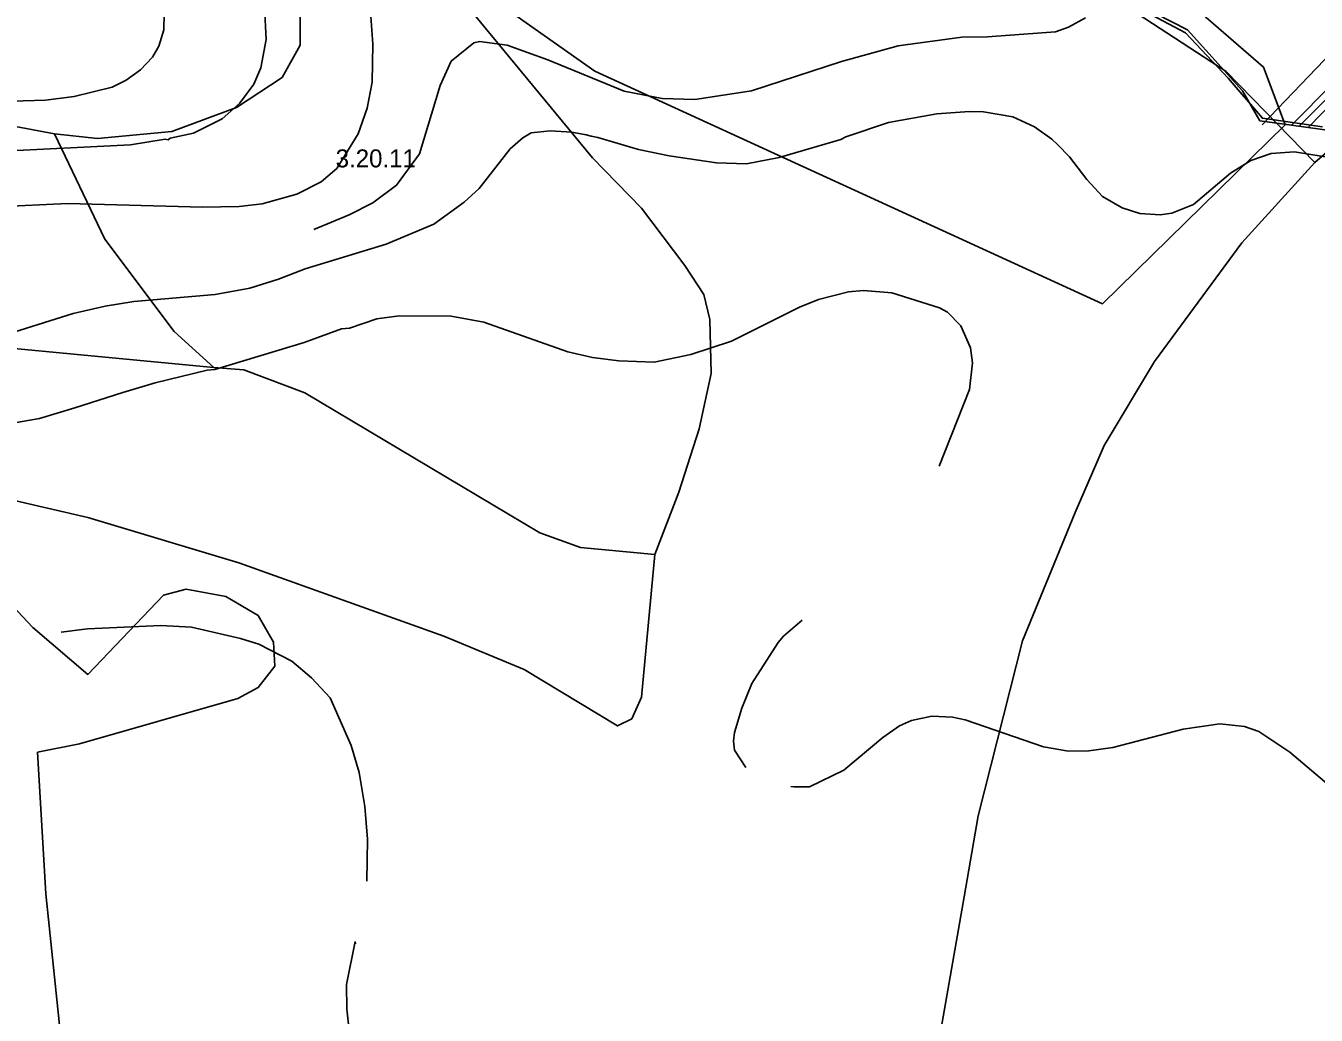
# Model space of a CAD drawing. Extents: x -662500 to -655523, y -1056000 to -1049993.
# Drawn here: x -661264 to -660726, y -1053965 to -1053552 of the extents above; entities that cross this region are included whole.
import ezdxf

# ---------------------------------------------------------------- set-up
doc = ezdxf.new("R2010")
doc.units = 0
for name, color, linetype in [('58', 7, 'Continuous'), ('Vrstva 1', 7, 'Continuous'), ('Vrstva 24', 7, 'Continuous'), ('Vrstva 32', 7, 'Continuous'), ('Vrstva 37', 7, 'Continuous'), ('Vrstva 5', 7, 'Continuous'), ('Vrstva 51', 7, 'Continuous'), ('Vrstva 7', 7, 'Continuous')]:
    doc.layers.add(name, color=color, linetype=linetype)

msp = doc.modelspace()

# ---------------------------------------------------------------- linework, layer by layer
at = {"layer": '58'}
msp.add_lwpolyline([(-660722.92, -1053594.62), (-660747.91, -1053591.01), (-660762.26, -1053574.33), (-660780.1, -1053555.32), (-660805.82, -1053541.62)], dxfattribs=at)
at = {"layer": 'Vrstva 1'}
for points in [[(-660749.01, -1053592.05), (-660756.28, -1053579.6), (-660779.23, -1053554.07), (-660805.9, -1053540.3)], [(-660438.94, -1053983.58), (-660410.34, -1053829.44), (-660408.79, -1053821.07), (-660408.56, -1053819.81), (-660407.77, -1053814.99), (-660398.86, -1053759.98), (-660378.28, -1053653.76), (-660412.36, -1053647.26), (-660481.41, -1053634.1), (-660522.43, -1053627.05), (-660591.82, -1053615.12), (-660653.75, -1053605.31), (-660728.84, -1053594.86), (-660735.74, -1053593.9), (-660749.01, -1053592.05)]]:
    msp.add_lwpolyline(points, dxfattribs=at)
at = {"layer": 'Vrstva 24'}
for points in [[(-661088, -1053355.5), (-661106, -1053352.5), (-661119, -1053355), (-661133.5, -1053361.5), (-661158.5, -1053380.5), (-661171.5, -1053398.5), (-661180, -1053425.5), (-661178.5, -1053461.5), (-661169.5, -1053488.5), (-661160, -1053506.5), (-661149.5, -1053542.5), (-661149.5, -1053560.5), (-661157, -1053574), (-661176, -1053586.5), (-661203, -1053596.5), (-661234, -1053599.5), (-661252, -1053597.5)], [(-661001.5, -1053773), (-660991.5, -1053747), (-660983, -1053720.5), (-660978, -1053697.5), (-660978.5, -1053675), (-660981, -1053664.5), (-660989, -1053652.5), (-661007, -1053628.5), (-661027.5, -1053607.5), (-661079.5, -1053544.5), (-661099.5, -1053509.5), (-661117, -1053463.5), (-661120.5, -1053436.5), (-661117, -1053400.5), (-661107.5, -1053378), (-661096, -1053362.5), (-661088, -1053355.5)], [(-660726, -1053609.5), (-660746.75, -1053588.19), (-660763, -1053571.5), (-660803, -1053545.5), (-660863.5, -1053530), (-660875.5, -1053525), (-660916, -1053497.5), (-660931, -1053485.5)], [(-660726, -1053609.5), (-660705.14, -1053591.51), (-660671.5, -1053562.5), (-660660, -1053547.5)], [(-661185.5, -1053695), (-661301, -1053684), (-661359, -1053670), (-661461.5, -1053632.5), (-661511.5, -1053619), (-661574.5, -1053608), (-661636, -1053600.5), (-661701, -1053596.5), (-661815.5, -1053587.5), (-661858, -1053587.5)], [(-661252, -1053597.5), (-661270.5, -1053594)], [(-661252, -1053597.5), (-661231, -1053641.5), (-661202, -1053680), (-661185.5, -1053695)], [(-660911, -1054178.5), (-660888, -1054130), (-660876.5, -1054089.5), (-660875.5, -1054053.5), (-660883, -1054011.5), (-660884.37, -1054000), (-660885.5, -1053990.5), (-660872.42, -1053915.83), (-660866.5, -1053882), (-660848, -1053809), (-660826, -1053755.5), (-660816.62, -1053733.62), (-660814, -1053727.5), (-660793, -1053692.5), (-660756.5, -1053643), (-660726, -1053609.5)], [(-661001.5, -1053773), (-661007, -1053832.5), (-661011, -1053841.5), (-661017, -1053844.5), (-661056, -1053821), (-661089.5, -1053807), (-661175, -1053776.5), (-661238, -1053757.5), (-661296.5, -1053744), (-661341, -1053727.5), (-661428, -1053677.5), (-661441.5, -1053671.5), (-661457, -1053664.5), (-661466, -1053663), (-661476, -1053660.5), (-661516, -1053659.5), (-661560.5, -1053660.5), (-661618.5, -1053666.5), (-661717, -1053683.5), (-661723, -1053683.5)], [(-661246.7, -1054000), (-661255.5, -1053914.5), (-661259, -1053855.5), (-661241.5, -1053852), (-661175.5, -1053833), (-661167, -1053828.5), (-661160, -1053819.5), (-661160.5, -1053809.5), (-661167, -1053798.5), (-661180.5, -1053790.5), (-661197, -1053787.5), (-661206.5, -1053790), (-661238, -1053823), (-661261, -1053803.5), (-661278, -1053785.5), (-661300.5, -1053776), (-661437, -1053726.5), (-661515.5, -1053701.5), (-661544, -1053699.5), (-661598, -1053702.5), (-661562, -1053690.5), (-661657, -1053696.5), (-661706, -1053697)], [(-661185.5, -1053695), (-661173, -1053696), (-661147.5, -1053705.5), (-661049.5, -1053764), (-661032.5, -1053770), (-661001.5, -1053773)]]:
    msp.add_lwpolyline(points, dxfattribs=at)
at = {"layer": 'Vrstva 32'}
msp.add_lwpolyline([(-660732.59, -1053594.34), (-660658.93, -1053520.19), (-660602.39, -1053463.45), (-660566.95, -1053428.59), (-660489, -1053349.86), (-660473.49, -1053335.13), (-660419.3, -1053279.86), (-660364.42, -1053224.74), (-660340.86, -1053200.88), (-660320.07, -1053179.63)], dxfattribs=at)
at = {"layer": 'Vrstva 37'}
msp.add_lwpolyline([(-661177.27, -1053298.13), (-661011.27, -1053272.33), (-660950.35, -1053416.85), (-660917.78, -1053483.08), (-660790.25, -1053532.64), (-660747.55, -1053569.67), (-660738.48, -1053593.77), (-660814.61, -1053668.4), (-661026.54, -1053571.34), (-661076.33, -1053536.24), (-661164.49, -1053527.45), (-661164.49, -1053425.3)], close=True, dxfattribs=at)
at = {"layer": 'Vrstva 5'}
for points in [[(-660718.56, -1053576.57), (-660735.74, -1053593.9), (-660749.01, -1053592.05), (-660756.28, -1053579.6), (-660779.23, -1053554.07), (-660805.9, -1053540.3)], [(-660717.01, -1053582.82), (-660728.84, -1053594.86), (-660735.74, -1053593.9), (-660718.56, -1053576.57)], [(-660717.01, -1053582.82), (-660728.84, -1053594.86), (-660659.38, -1053604.53)]]:
    msp.add_lwpolyline(points, dxfattribs=at)
at = {"layer": 'Vrstva 51'}
msp.add_lwpolyline([(-660747.98, -1053593.81), (-660615.41, -1053455.28), (-660562.74, -1053417.28), (-660448.34, -1053299.63)], dxfattribs=at)
at = {"layer": 'Vrstva 7'}
for p, q in [((-661163.58, -1053558.13), (-661164.29, -1053544.52)), ((-661119.08, -1053560.11), (-661120.21, -1053544.52)), ((-661206.38, -1053554.16), (-661206.23, -1053547.35)), ((-660828.84, -1053553.02), (-660821.76, -1053549.06)), ((-661208.36, -1053560.96), (-661206.38, -1053554.16)), ((-660862.58, -1053557.06), (-660834.23, -1053555.01)), ((-660834.23, -1053555.01), (-660828.84, -1053553.02)), ((-661211.05, -1053565.5), (-661208.36, -1053560.96)), ((-661165.85, -1053570.03), (-661163.58, -1053558.13)), ((-661119.36, -1053575.98), (-661119.08, -1053560.11)), ((-661086.48, -1053567.2), (-661076.99, -1053559.54)), ((-661076.99, -1053559.54), (-661074.58, -1053558.98)), ((-661074.58, -1053558.98), (-661063.1, -1053560.53)), ((-661063.1, -1053560.53), (-661046.09, -1053566.63)), ((-660923.51, -1053567.34), (-660899.99, -1053560.82)), ((-660899.99, -1053560.82), (-660873.34, -1053557.13)), ((-660873.34, -1053557.13), (-660862.58, -1053557.06)), ((-661216.01, -1053570.88), (-661211.05, -1053565.5)), ((-661091.02, -1053577.4), (-661086.48, -1053567.2)), ((-661046.09, -1053566.63), (-661014.21, -1053579.67)), ((-660961.07, -1053579.52), (-660923.51, -1053567.34)), ((-661221.97, -1053575.13), (-661216.01, -1053570.88)), ((-661168.78, -1053576.77), (-661165.85, -1053570.03)), ((-661243.79, -1053581.93), (-661227.92, -1053578.11)), ((-661227.92, -1053578.11), (-661221.97, -1053575.13)), ((-661174.77, -1053584.91), (-661168.78, -1053576.77)), ((-661121.49, -1053586.75), (-661119.36, -1053575.98)), ((-661099.66, -1053605.88), (-661091.02, -1053577.4)), ((-661269.58, -1053583.92), (-661255.69, -1053583.49)), ((-661255.69, -1053583.49), (-661243.79, -1053581.93)), ((-661014.21, -1053579.67), (-660998.34, -1053582.78)), ((-660998.34, -1053582.78), (-660984.73, -1053583.21)), ((-660984.73, -1053583.21), (-660961.07, -1053579.52)), ((-661182, -1053591.29), (-661174.77, -1053584.91)), ((-661125.17, -1053597.52), (-661121.49, -1053586.75)), ((-660883.83, -1053589.16), (-660870.22, -1053588.17)), ((-660870.22, -1053588.17), (-660864.27, -1053588.31)), ((-660864.27, -1053588.31), (-660852.09, -1053590.44)), ((-661193.91, -1053597.24), (-661182, -1053591.29)), ((-660921.81, -1053598.8), (-660903.95, -1053592.85)), ((-660903.95, -1053592.85), (-660883.83, -1053589.16)), ((-660852.09, -1053590.44), (-660843.02, -1053594.55)), ((-661220.27, -1053602.06), (-661205.81, -1053599.79)), ((-661205.81, -1053599.79), (-661204.53, -1053600.07)), ((-661204.53, -1053600.07), (-661203.68, -1053599.36)), ((-661203.68, -1053599.36), (-661193.91, -1053597.24)), ((-661134.1, -1053611.98), (-661125.17, -1053597.52)), ((-661061.83, -1053603.76), (-661056.58, -1053599.22)), ((-661056.58, -1053599.22), (-661053.04, -1053597.1)), ((-661053.04, -1053597.1), (-661045.1, -1053596.25)), ((-661045.1, -1053596.25), (-661036.03, -1053596.81)), ((-661036.03, -1053596.81), (-661030.08, -1053597.95)), ((-661030.08, -1053597.95), (-661027.99, -1053598.52)), ((-661027.99, -1053598.52), (-661025.26, -1053599.08)), ((-661025.26, -1053599.08), (-661008.26, -1053604.04)), ((-660923.79, -1053599.93), (-660921.81, -1053598.8)), ((-660843.02, -1053594.55), (-660835.78, -1053599.76)), ((-660835.78, -1053599.76), (-660833.38, -1053601.92)), ((-661283.75, -1053605.32), (-661220.27, -1053602.06)), ((-661074.72, -1053620.34), (-661061.83, -1053603.76)), ((-661008.26, -1053604.04), (-660995.5, -1053606.73)), ((-660949.59, -1053607.44), (-660923.79, -1053599.93)), ((-660833.38, -1053601.92), (-660828.42, -1053607.16)), ((-660744.22, -1053605.78), (-660734.53, -1053605.06)), ((-660734.53, -1053605.06), (-660717.45, -1053607.87)), ((-661109.3, -1053618.92), (-661099.66, -1053605.88)), ((-660995.5, -1053606.73), (-660975.66, -1053609.57)), ((-660975.66, -1053609.57), (-660963.19, -1053609.99)), ((-660963.19, -1053609.99), (-660949.59, -1053607.44)), ((-660828.42, -1053607.16), (-660821.19, -1053616.51)), ((-660761.32, -1053613.94), (-660752.83, -1053608.65)), ((-660752.83, -1053608.65), (-660744.22, -1053605.78)), ((-661140.62, -1053617.51), (-661134.1, -1053611.98)), ((-660776.69, -1053627), (-660761.32, -1053613.94)), ((-661150.82, -1053622.75), (-661140.62, -1053617.51)), ((-661119.08, -1053626.29), (-661109.3, -1053618.92)), ((-661080.96, -1053626.01), (-661074.72, -1053620.34)), ((-660821.19, -1053616.51), (-660814.67, -1053623.6)), ((-661287.16, -1053628.56), (-661246.34, -1053626.57)), ((-661246.34, -1053626.57), (-661190.22, -1053628.13)), ((-661174.92, -1053627.85), (-661165.28, -1053626.72)), ((-661165.28, -1053626.72), (-661150.82, -1053622.75)), ((-661129, -1053631.25), (-661119.08, -1053626.29)), ((-661093.71, -1053635.15), (-661080.96, -1053626.01)), ((-660814.67, -1053623.6), (-660806.45, -1053628.42)), ((-661190.22, -1053628.13), (-661174.92, -1053627.85)), ((-661143.74, -1053637.42), (-661129, -1053631.25)), ((-660806.45, -1053628.42), (-660799.08, -1053630.68)), ((-660799.08, -1053630.68), (-660790.58, -1053631.25)), ((-660790.58, -1053631.25), (-660785.76, -1053630.54)), ((-660785.76, -1053630.54), (-660776.69, -1053627)), ((-661113.57, -1053643.53), (-661093.71, -1053635.15)), ((-661147.42, -1053653.85), (-661113.57, -1053643.53)), ((-661170.38, -1053661.86), (-661158.48, -1053658.18)), ((-661158.48, -1053658.18), (-661147.42, -1053653.85)), ((-661184.84, -1053664.55), (-661170.38, -1053661.86)), ((-660933.15, -1053666.68), (-660920.68, -1053663.42)), ((-660920.68, -1053663.42), (-660914.44, -1053662.85)), ((-660914.44, -1053662.85), (-660902.54, -1053663.85)), ((-660902.54, -1053663.85), (-660882.62, -1053670.15)), ((-661244.21, -1053672.49), (-661230.75, -1053669.37)), ((-661230.75, -1053669.37), (-661218.85, -1053667.39)), ((-661218.85, -1053667.39), (-661184.84, -1053664.55)), ((-660969.43, -1053683.97), (-660941.08, -1053669.8)), ((-660941.08, -1053669.8), (-660933.15, -1053666.68)), ((-661278.37, -1053683.26), (-661244.21, -1053672.49)), ((-661128.86, -1053678.58), (-661117.39, -1053674.67)), ((-661117.39, -1053674.67), (-661108.12, -1053673.47)), ((-661108.12, -1053673.47), (-661086.48, -1053673.62)), ((-661086.48, -1053673.62), (-661072.74, -1053676.03)), ((-660882.62, -1053670.15), (-660879.3, -1053671.92)), ((-660879.3, -1053671.92), (-660873.77, -1053677.59)), ((-661147.71, -1053684.54), (-661132.26, -1053678.87)), ((-661132.26, -1053678.87), (-661128.86, -1053678.58)), ((-661072.74, -1053676.03), (-661037.73, -1053688.5)), ((-660873.77, -1053677.59), (-660869.8, -1053686.8)), ((-661184.98, -1053695.87), (-661147.71, -1053684.54)), ((-660986.43, -1053689.5), (-660969.43, -1053683.97)), ((-661037.73, -1053688.5), (-661027.53, -1053690.77)), ((-661027.53, -1053690.77), (-661016.48, -1053692.19)), ((-661001.74, -1053692.76), (-660986.43, -1053689.5)), ((-660869.8, -1053686.8), (-660868.95, -1053693.04)), ((-661209.9, -1053701.32), (-661188.24, -1053696.16)), ((-661188.24, -1053696.16), (-661184.98, -1053695.87)), ((-661016.48, -1053692.19), (-661001.74, -1053692.76)), ((-660868.95, -1053693.04), (-660870.1, -1053704.11)), ((-661223.38, -1053705.37), (-661209.9, -1053701.32)), ((-661243.51, -1053711.75), (-661223.38, -1053705.37)), ((-660870.1, -1053704.11), (-660882.86, -1053736.16)), ((-661258.24, -1053716.28), (-661243.51, -1053711.75)), ((-661271.85, -1053718.69), (-661258.24, -1053716.28)), ((-661249.17, -1053805.44), (-661238.12, -1053804)), ((-661238.12, -1053804), (-661207.51, -1053802.59)), ((-661207.51, -1053802.59), (-661194.76, -1053803.29)), ((-661194.76, -1053803.29), (-661174.35, -1053807.97)), ((-660939.91, -1053800.41), (-660947.74, -1053807.12)), ((-661174.35, -1053807.97), (-661166.7, -1053810.38)), ((-660949.96, -1053809.75), (-660960.92, -1053826.82)), ((-660947.74, -1053807.12), (-660949.96, -1053809.75)), ((-661166.7, -1053810.38), (-661152.95, -1053817.47)), ((-661152.95, -1053817.47), (-661144.73, -1053824.41)), ((-661144.73, -1053824.41), (-661136.94, -1053832.77)), ((-660960.92, -1053826.82), (-660965.18, -1053837.02)), ((-661136.94, -1053832.77), (-661128.15, -1053852.61)), ((-660965.18, -1053837.02), (-660968.15, -1053847.23)), ((-660894.32, -1053842.27), (-660885.81, -1053840.42)), ((-660885.81, -1053840.42), (-660877.31, -1053840.85)), ((-660877.31, -1053840.85), (-660871.93, -1053842.01)), ((-660871.93, -1053842.01), (-660839.33, -1053853.18)), ((-660968.15, -1053847.23), (-660968.58, -1053850.91)), ((-660906.36, -1053849.35), (-660899.42, -1053844.39)), ((-660899.42, -1053844.39), (-660894.32, -1053842.27)), ((-660810.42, -1053853.46), (-660780.94, -1053845.81)), ((-660780.94, -1053845.81), (-660765.64, -1053843.68)), ((-660765.64, -1053843.68), (-660755.44, -1053844.68)), ((-660755.44, -1053844.68), (-660749.48, -1053846.8)), ((-660749.48, -1053846.8), (-660736.45, -1053855.45)), ((-661128.15, -1053852.61), (-661124.75, -1053863.95)), ((-660968.58, -1053850.91), (-660968.15, -1053854.6)), ((-660922.66, -1053862.96), (-660906.36, -1053849.35)), ((-660968.15, -1053854.6), (-660963.53, -1053861.87)), ((-660839.33, -1053853.18), (-660828.84, -1053855.02)), ((-660828.84, -1053855.02), (-660820.34, -1053854.88)), ((-660820.34, -1053854.88), (-660810.42, -1053853.46)), ((-660736.45, -1053855.45), (-660720.29, -1053869.19)), ((-660936.97, -1053869.9), (-660922.66, -1053862.96)), ((-661124.75, -1053863.95), (-661122.48, -1053878.12)), ((-660944.75, -1053869.77), (-660943.52, -1053869.96)), ((-660943.52, -1053869.96), (-660936.97, -1053869.9)), ((-661122.48, -1053878.12), (-661121.35, -1053891.73)), ((-661121.35, -1053891.73), (-661121.65, -1053909.19)), ((-661126.45, -1053934.38), (-661130.13, -1053952.38)), ((-661126.31, -1053935.39), (-661126.45, -1053934.38)), ((-661130.13, -1053952.38), (-661129.99, -1053962.58)), ((-661129.99, -1053962.58), (-661128.57, -1053975.34))]:
    msp.add_line(p, q, dxfattribs=at)

# ---------------------------------------------------------------- texts
at = {"layer": 'Vrstva 24'}
msp.add_text('3.20.11', height=7.5, dxfattribs=at).set_placement((-661134.62, -1053611.51))

doc.saveas('drawing.dxf')
